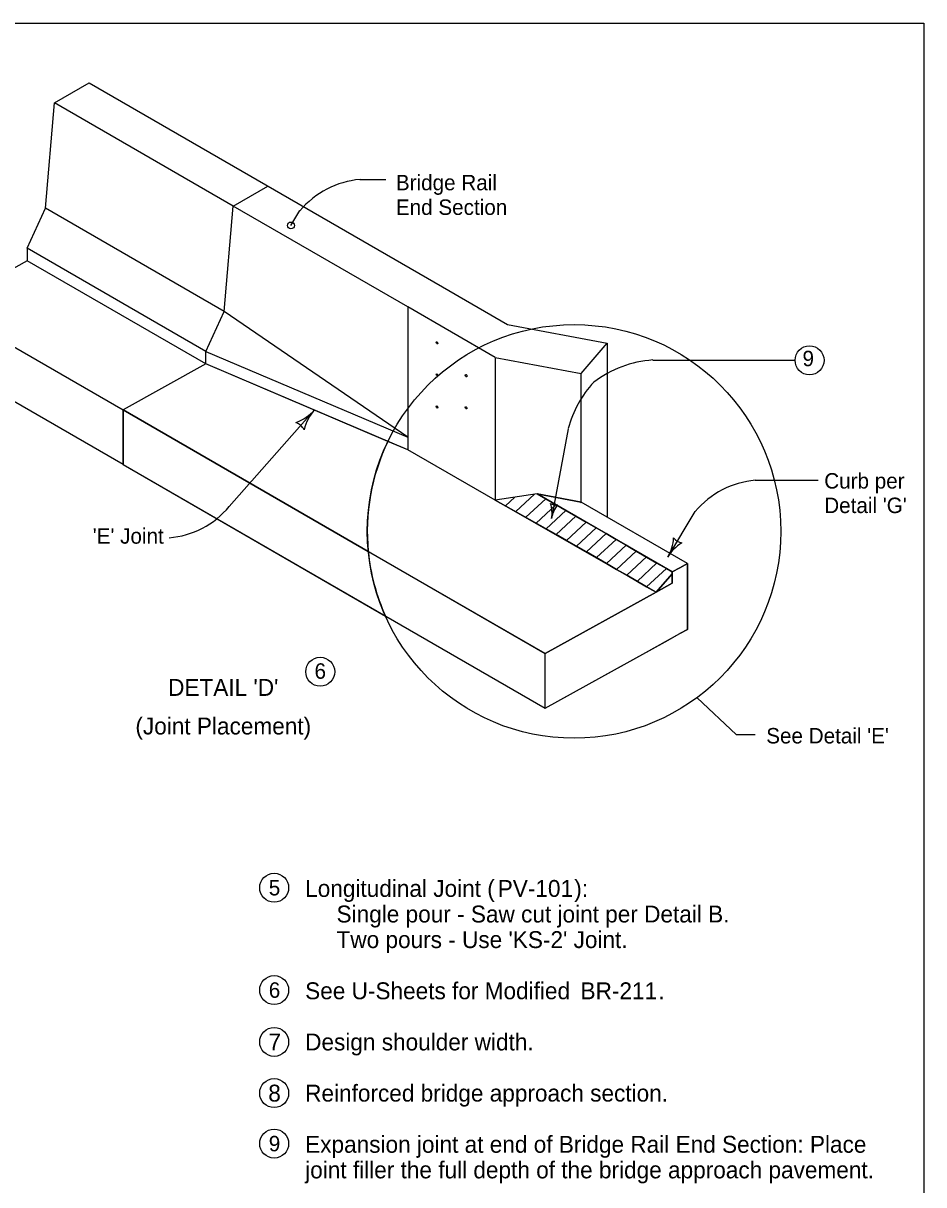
# Model space of a CAD drawing. Extents: x 5546 to 81668, y 3174 to 15999.
# Drawn here: x 19534 to 20468, y 8741 to 9944 of the extents above; entities that cross this region are included whole.
import ezdxf

# ---------------------------------------------------------------- set-up
doc = ezdxf.new("R2010")
doc.units = 0
for name, color, linetype in [('Level 61', 7, 'Continuous'), ('PC_REBAR', 7, 'Continuous'), ('PS_BOLT', 7, 'Continuous'), ('PS_CONST', 7, 'Continuous'), ('PS_DIM', 7, 'Continuous'), ('SheetAddenda', 7, 'Continuous'), ('Table Border', 7, 'Continuous')]:
    doc.layers.add(name, color=color, linetype=linetype)

msp = doc.modelspace()

# ---------------------------------------------------------------- linework, layer by layer
at = {"layer": 'Level 61'}
msp.add_lwpolyline([(17332.5, 9944), (20467.5, 9944), (20467.5, 7924), (17332.5, 7924)], close=True, dxfattribs=at)
at = {"layer": 'PC_REBAR'}
msp.add_circle((19811.9, 9734.6), 3.54, dxfattribs=at)
at = {"layer": 'PS_CONST'}
for centre, radius, start, end in [((20165.9, 9413.3), 42.5, 328.7108, 356.7833), ((20220.7, 9421.7), 16.4, 220.9775, 256.4442), ((20238.5, 9369.2), 42.5, 120.6383, 148.7108)]:
    msp.add_arc(centre, radius, start, end, dxfattribs=at)
at = {"layer": 'PS_DIM'}
for p, q in [((19602.9, 9882.2), (19968.9, 9670.9)), ((19752, 9754.7), (19567, 9861.5)), ((19883.4, 9782.2), (19910.3, 9782.2)), ((19742.6, 9645.6), (19557.6, 9752.4)), ((19933, 9650.2), (19752, 9754.7)), ((19811.9, 9734.6), (19821.2, 9749.9)), ((19723.7, 9604.2), (19538.7, 9711)), ((19538.7, 9711), (19538.7, 9697.9)), ((19968.9, 9670.9), (20036.2, 9632)), ((19933, 9650.2), (19933, 9502.3)), ((20023.6, 9597.9), (19933, 9650.2)), ((20036.2, 9632), (20139.4, 9612.6)), ((20139.4, 9612.6), (20139.4, 9432.6)), ((19723.7, 9591.1), (19637.9, 9543.5)), ((19723.7, 9591.1), (19637.9, 9543.5)), ((19912.4, 9511), (19723.7, 9591.1)), ((19933, 9502.3), (19723.7, 9591.1)), ((20023.6, 9597.9), (20023.6, 9450)), ((20023.6, 9597.9), (20112.5, 9581.2)), ((20186.8, 9595.2), (20334.3, 9595.2)), ((20112.5, 9448.1), (20112.5, 9581.2)), ((19637.9, 9543.5), (19637.9, 9486.9)), ((19892, 9396.8), (19637.9, 9543.5)), ((19637.9, 9543.5), (19637.9, 9486.9)), ((19637.9, 9543.5), (19892, 9396.8)), ((19637.9, 9543.5), (20075.1, 9291.1)), ((19836.4, 9543.8), (19748, 9443.5)), ((20099, 9524.1), (20081.8, 9431.1)), ((19933, 9502.3), (19912.4, 9511)), ((20023.6, 9450), (19933, 9502.3)), ((20023.6, 9450), (19933, 9502.3)), ((19637.9, 9486.9), (20075.1, 9234.5)), ((19637.9, 9486.9), (19909.8, 9329.9)), ((20293, 9470.7), (20358.2, 9470.7)), ((20066.9, 9456.7), (20023.6, 9450)), ((20066.9, 9456.7), (20023.6, 9450)), ((20064.1, 9456.2), (20044.7, 9438.2)), ((20107.2, 9433.4), (20066.9, 9456.7)), ((20112.5, 9448.1), (20066.9, 9456.7)), ((20066.9, 9456.7), (20107.2, 9433.4)), ((20207, 9375.8), (20066.9, 9456.7)), ((20066.9, 9456.7), (20112.5, 9448.1)), ((20086.8, 9414.4), (20023.6, 9450)), ((20023.6, 9450), (20023.6, 9450)), ((20023.6, 9450), (20086.8, 9414.4)), ((20186.5, 9356.8), (20023.6, 9450)), ((20190.1, 9354.8), (20023.6, 9450)), ((20023.6, 9450), (20023.6, 9450)), ((20043.9, 9453.1), (20034.1, 9444.1)), ((20075.9, 9451.5), (20055.2, 9432.3)), ((20086.4, 9445.4), (20065.8, 9426.4)), ((20222.7, 9384.5), (20112.5, 9448.1)), ((20222.7, 9384.5), (20112.5, 9448.1)), ((20096.8, 9439.4), (20076.4, 9420.4)), ((20086.8, 9414.4), (20107.2, 9433.4)), ((20107.2, 9433.4), (20086.8, 9414.4)), ((20107.2, 9433.4), (20086.8, 9414.4)), ((20117.6, 9427.4), (20107.2, 9433.4)), ((20107.2, 9433.4), (20117.6, 9427.4)), ((20202.2, 9391.2), (20230.8, 9438.3)), ((20097.2, 9408.4), (20117.6, 9427.4)), ((20117.6, 9427.4), (20097.2, 9408.4)), ((20117.6, 9427.4), (20097.2, 9408.4)), ((20107.6, 9402.4), (20128, 9421.4)), ((20128, 9421.4), (20107.6, 9402.4)), ((20128, 9421.4), (20107.6, 9402.4)), ((20128, 9421.4), (20117.6, 9427.4)), ((20117.6, 9427.4), (20128, 9421.4)), ((20138.4, 9415.4), (20128, 9421.4)), ((20128, 9421.4), (20138.4, 9415.4)), ((20086.8, 9414.4), (20097.2, 9408.4)), ((20097.2, 9408.4), (20107.6, 9402.4)), ((20118, 9396.4), (20138.4, 9415.4)), ((20138.4, 9415.4), (20118, 9396.4)), ((20138.4, 9415.4), (20118, 9396.4)), ((20148.7, 9409.4), (20128.6, 9390.8)), ((19892, 9396.8), (20075.1, 9291.1)), ((20075.1, 9291.1), (19892, 9396.8)), ((20107.6, 9402.4), (20118, 9396.4)), ((20118, 9396.4), (20138.8, 9384.4)), ((20138.8, 9384.4), (20159.2, 9403.4)), ((20159.2, 9403.4), (20138.8, 9384.4)), ((20159.2, 9403.4), (20138.8, 9384.4)), ((20149.2, 9378.4), (20169.6, 9397.4)), ((20169.6, 9397.4), (20149.2, 9378.4)), ((20169.6, 9397.4), (20149.2, 9378.4)), ((20169.6, 9397.4), (20159.2, 9403.4)), ((20159.2, 9403.4), (20169.6, 9397.4)), ((20138.8, 9384.4), (20149.2, 9378.4)), ((20180.1, 9391.3), (20159.7, 9372.3)), ((20191.1, 9385), (20170.7, 9366)), ((20222.7, 9384.5), (20214.8, 9380.1)), ((20214.8, 9380.1), (20222.7, 9384.5)), ((20222.7, 9384.5), (20214.8, 9380.1)), ((20222.7, 9316.2), (20222.7, 9384.5)), ((20149.2, 9378.4), (20159.7, 9372.3)), ((20159.7, 9372.3), (20180.4, 9360.4)), ((20180.4, 9360.4), (20200.8, 9379.3)), ((20200.8, 9379.3), (20180.4, 9360.4)), ((20200.8, 9379.3), (20180.4, 9360.4)), ((20190.1, 9354.8), (20207, 9373.9)), ((20207, 9373.9), (20190.1, 9354.8)), ((20190.1, 9354.8), (20207, 9373.9)), ((20207, 9375.8), (20200.8, 9379.3)), ((20200.8, 9379.3), (20207, 9375.8)), ((20214.8, 9380.1), (20207, 9375.8)), ((20207, 9375.8), (20214.8, 9380.1)), ((20214.8, 9380.1), (20207, 9375.8)), ((20207, 9373.9), (20207, 9375.8)), ((20207, 9364.1), (20207, 9375.8)), ((20207, 9364.1), (20207, 9373.9)), ((20075.1, 9291.1), (20207, 9364.1)), ((20180.4, 9360.4), (20186.5, 9356.8)), ((20207, 9364.1), (20190.1, 9354.8)), ((20190.1, 9354.8), (20207, 9364.1)), ((20075.1, 9291.1), (20190.1, 9354.8)), ((20190.1, 9354.8), (20075.1, 9291.1)), ((20190.1, 9354.8), (20186.5, 9356.8)), ((20186.5, 9356.8), (20190.1, 9354.8)), ((19909.8, 9329.9), (20075.1, 9234.5)), ((20179.6, 9292.3), (20214.8, 9311.9)), ((20199.7, 9303.5), (20214.8, 9311.9)), ((20214.8, 9311.9), (20222.7, 9316.2)), ((20222.7, 9316.2), (20214.8, 9311.9)), ((20075.1, 9234.5), (20199.7, 9303.5)), ((20075.1, 9234.5), (20075.1, 9291.1)), ((20232.6, 9245.5), (20273, 9207.5)), ((20273, 9207.5), (20292.8, 9207.5))]:
    msp.add_line(p, q, dxfattribs=at)
for points in [[(19567, 9861.5), (19602.9, 9882.2)], [(19538.7, 9711), (19557.6, 9752.4), (19567, 9861.5)], [(19752, 9754.7), (19787.9, 9775.4)], [(19723.7, 9591.1), (19723.7, 9604.2), (19742.6, 9645.6), (19752, 9754.7)], [(19538.7, 9697.9), (19452.9, 9650.3)], [(19723.7, 9591.1), (19538.7, 9697.9)], [(19452.9, 9650.3), (19637.9, 9543.5)], [(19723.7, 9604.2), (19933, 9515.4), (19742.6, 9645.6)], [(20112.5, 9581.2), (20139.4, 9612.6)], [(19637.9, 9486.9), (19452.9, 9593.7)], [(19723.7, 9591.1), (19637.9, 9543.5)], [(19637.9, 9486.9), (19637.9, 9543.5)], [(20023.6, 9450), (20023.6, 9450)], [(20112.5, 9448.1), (20111.7, 9447.7), (20112.5, 9448.1)], [(20107.6, 9402.4), (20097.2, 9408.4), (20086.8, 9414.4)], [(20159.2, 9403.4), (20148.7, 9409.4), (20138.4, 9415.4)], [(20138.4, 9415.4), (20148.7, 9409.4), (20159.2, 9403.4)], [(20138.8, 9384.4), (20118, 9396.4), (20107.6, 9402.4)], [(20200.8, 9379.3), (20191.1, 9384.9), (20169.6, 9397.4)], [(20169.6, 9397.4), (20191.1, 9384.9), (20200.8, 9379.3)], [(20186.5, 9356.8), (20180.4, 9360.4), (20159.7, 9372.3), (20149.2, 9378.4), (20138.8, 9384.4)], [(20222.7, 9384.5), (20222.7, 9316.2)], [(20207, 9375.8), (20207, 9373.9), (20207, 9364.1)], [(20075.1, 9234.5), (20179.6, 9292.3), (20199.7, 9303.5)]]:
    msp.add_lwpolyline(points, dxfattribs=at)
for centre, radius in [((20105.2, 9417.7), 214.2), ((20349.2, 9594.9), 15), ((19842.2, 9272.4), 15), ((19794.5, 9048.7), 15), ((19794.5, 8942.7), 15), ((19794.5, 8889), 15), ((19794.5, 8836), 15), ((19794.5, 8783.7), 15)]:
    msp.add_circle(centre, radius, dxfattribs=at)
for centre, radius, start, end in [((19891.1, 9691.5), 91, 94.8409, 140.1467), ((20195.7, 9478.1), 117.5, 94.3399, 126.627), ((20212.4, 9493.2), 117.5, 137.5971, 164.7195), ((19800.2, 9575.8), 48.4, 290.4433, 318.5158), ((19872.7, 9511.8), 48.4, 138.5158, 166.5883), ((19809.6, 9513.4), 18.7, 30.7825, 66.2492), ((20105.2, 9417.7), 214.2, 154.1687, 185.6063), ((20105.2, 9417.7), 214.2, 154.1687, 185.6063), ((20300.7, 9380), 91, 94.8409, 140.1467), ((19678.1, 9501.8), 91, 274.8409, 320.1467), ((20086.7, 9457.7), 12.5, 241.782, 277.2487), ((20050.1, 9437), 32.3, 349.5153, 17.5878), ((20113.5, 9425.2), 32.3, 141.4428, 169.5153), ((20105.2, 9417.7), 214.2, 185.6063, 204.2018), ((20105.2, 9417.7), 214.2, 185.6063, 204.2018)]:
    msp.add_arc(centre, radius, start, end, dxfattribs=at)
for centre in [(19963.2, 9613), (19963.2, 9579.8), (19993.4, 9579), (19963.2, 9546.6), (19993.4, 9545.8)]:
    msp.add_ellipse(centre, major_axis=(0.67, -1.15), ratio=0.57735, dxfattribs=at)
at = {"layer": 'Table Border'}
msp.add_line((19637.9, 9486.9), (20075.1, 9234.5), dxfattribs=at)

# ---------------------------------------------------------------- texts
at = {"layer": 'PS_BOLT'}
for s, height, p in [('6', 16, (19836.3, 9265.1)), ('(Joint Placement)', 17.5, (19650.7, 9207.4))]:
    msp.add_text(s, height=height, dxfattribs=at).set_placement(p)
at = {"layer": 'PS_DIM'}
for s, height, p in [('Bridge Rail ', 16, (19920.6, 9771)), ('End Section', 16, (19920.6, 9745.5)), ('Curb per', 16, (20364.4, 9462.1)), ("Detail 'G'", 16, (20364.4, 9436.7)), ("'E' Joint", 16, (19606.5, 9405)), ("DETAIL 'D'", 17.5, (19684.6, 9247.4)), ("See Detail 'E'", 16, (20304.3, 9198.1))]:
    msp.add_text(s, height=height, dxfattribs=at).set_placement(p)
at = {"layer": 'SheetAddenda'}
for s, height, p in [('9', 16, (20341.9, 9588.8)), ('5', 16, (19788.9, 9040.7)), ('Longitudinal Joint (', 17.5, (19826.6, 9039.2)), ('PV-101', 17.5, (20026.1, 9039.2)), ('):', 17.5, (20105.4, 9039.2)), ('     Single pour - Saw cut joint per Detail B.', 17.5, (19826.6, 9012.7)), ("     Two pours - Use 'KS-2' Joint.", 17.5, (19826.6, 8986.2)), ('6', 16, (19788.9, 8934.7)), ('See U-Sheets for Modified ', 17.5, (19826.6, 8933.2)), ('BR-211', 17.5, (20111.9, 8933.2)), ('.', 17.5, (20192.5, 8933.2)), ('7', 17.5, (19788.6, 8880.2)), ('Design shoulder width.', 17.5, (19826.6, 8880.2)), ('8', 17.5, (19788.4, 8827.2)), ('Reinforced bridge approach section.', 17.5, (19826.6, 8827.2)), ('9', 16, (19788.9, 8775.7)), ('Expansion joint at end of Bridge Rail End Section: Place', 17.5, (19826.6, 8774.2)), ('joint filler the full depth of the bridge approach pavement.', 17.5, (19826.6, 8747.7))]:
    msp.add_text(s, height=height, dxfattribs=at).set_placement(p)

doc.saveas('drawing.dxf')
